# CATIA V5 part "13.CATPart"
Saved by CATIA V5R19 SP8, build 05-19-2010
Part number: 13
Bounding box of the stored display mesh (mm): x -490 to -260.023, y 254.1 to 685.9, z -435.705 to -4.295
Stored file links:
  G:\EU_thinkMotion\CFAO_2010\MMS_groupe3\MMS_groupe3\A reprendre\bblot\BLOT\13.CATPart
  J:\CFAO_IFMA\Amortisseur.CATProduct
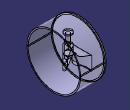
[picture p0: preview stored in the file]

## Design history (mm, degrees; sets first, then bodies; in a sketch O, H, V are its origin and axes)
Set1
  Point1 "F": linked copy from another document
  Line1 "as (BF)": linked copy from another document
  Point2 "D": linked copy from another document
  Line2 "ap": linked copy from another document
Set2
  Plane1: type OffsetPt, RefPlane yz-plane, RefPoint Point1
  Line3: type PtDir, RefPoint Point1, Direction Line2, Start 0, End 20
  Plane2: type OffsetPt, RefPlane Plane3, RefPoint Point2
  Plane3: stored without definition
  Line4 "D\"F\"": stored without definition
  DatumCurve1
  Plane4: stored without definition
  Plane5: type OffsetPt, RefPlane Plane6, RefPoint Point3
  Point3 "D": stored without definition
  Plane6 "Fig.3": stored without definition
Body1 (main body)
  Sketch1 on Plane1, origin (-400, 0, 0), H (0, 1, 0), V (0, 0, 1)
    line L1 (470, -220) -> (500, -220)
    line L2 (500, -220) -> (500, -160)
    line L3 (500, -160) -> (485, -160)
    line L4 (485, -160) -> (485, -80)
    line L5 (485, -80) -> (500, -80)
    point P6 (500, -80)
    line L6 (500, -80) -> (500, -70)
    line L7 (500, -70) -> (470, -70)
    line L8 (470, -70) -> (470, -220)
    reference projected point E1 (470, -220) from Line1
    construction line L9 (470, -249.3526) -> (470, -220)
    point P9 (470, -249.3526)
    axis line L10 (570, -190) -> (500, -190)
    point P10 (570, -190)
    point P11 (500, -190)
    reference projected point E2 (570, -190) from Point2
    distance L8 L4 = 15
    length L2 = 60
    length L6 = 10
    length L1 = 30
    length L4 = 80
    horizontal: L1 H, L3 H, L5 H, L7 H, L10 H
    vertical: L2 V, L4 V, L6 V, L8 V, L9 V
    coincidence: P6 L2, L8 E1, P9 L8, P10 E2, L2 L6
    midpoint: P11 L2
  Shaft1: profile Sketch1, axis Line3, angle 360
  Sketch2 on face of Shaft1 from Sketch1.L3, origin (0, 0, -160), H (1, 0, 0), V (0, 1, 0)
    arc A1 centre (-400, 470) radius 30 from (-415.2552, 495.8317) to (-378.9456, 448.6292) ccw
    line L1 (-415.2552, 495.8317) -> (-275.0851, 578.6106)
    arc A2 centre (-270, 570) radius 10 from (-262.9819, 562.8764) to (-275.0851, 578.6106) ccw
    point P4 (-270, 570)
    reference projected circle E1 centre (-400, 470) radius 30 from edge [face of Shaft1 from Sketch1.L6 | face of Shaft1 from Sketch1.L7]
    reference projected point E2 (-270, 570) from Point2
    reference projected point E3 (-270, 570) from Point2
    line L2 (-262.9819, 562.8764) -> (-378.9456, 448.6292)
    radius A2 = 10
    tangency: L1 A1, A2 L1, L2 A2, L2 A1
    coincidence: A1 E1, P4 E2, P4 E3
  Pad1: profile Sketch2, direction (0, 0, 1), up to face of Shaft1 from Sketch1.L1
  SolidCombine1: FirstComponentProfile Sketch6, FirstComponentDirection Sketch6, SecondComponentProfile Sketch7, SecondComponentDirection Sketch7
  Sketch3 on face of SolidCombine1 from Sketch7.L1, origin (-480, 0, 0), H (0, -1, 0), V (0, 0, 1)
    circle A1 centre (-470, -220) radius 215.9
    point P1 (-470, -220)
    reference projected line E1 through (-470, 0) direction (0, 1) from Line3
    reference projected point E2 (-470, -220) from Line1
    radius A1 = 215.9
    coincidence: P1 E1, P1 E2
  Pad2: profile Sketch3, direction (-1, 0, 0), length 10
  Sketch4 on start face of Pad2, origin (-480, 0, 0), H (0, 1, 0), V (0, 0, 1)
    circle A1 centre (470, -220) radius 215.9
    reference projected circle E1 centre (470, -220) radius 215.9 from edge [start face of Pad2 | face of Pad2 from Sketch3.A1]
    circle A2 centre (470, -220) radius 205.9
    distance A2 A1 = 10
    coincidence: A1 E1
    concentricity: A2 A1
  Pad3: profile Sketch4, direction (1, 0, 0), length 195
  Sketch5 on Plane2, origin (0, 0, -190), H (1, 0, 0), V (0, 1, 0)
    line L1 (-270.8385, 587.4913) -> (-253.309, 564.7029)
    line L2 (-253.309, 564.7029) -> (-288.9771, 537.266)
    line L3 (-288.9771, 537.266) -> (-306.5066, 560.0543)
    line L4 (-306.5066, 560.0543) -> (-270.8385, 587.4913)
    point P3 (-288.9771, 537.266)
    point P4 (-306.5066, 560.0543)
    reference projected line E1 (-400, 470) -> (-270, 570) from Line4
    reference projected arc E2 centre (-270, 570) radius 10 from (-262.9819, 562.8764) to (-275.0851, 578.6106) ccw from edge [face of Pad1 from Sketch2.A2 | start face of Pad1]
    reference projected line E3 (-275.0851, 578.6106) -> (-415.2552, 495.8317) from edge [face of Pad1 from Sketch2.L1 | face of Shaft1]
    reference projected line E4 (-378.9456, 448.6292) -> (-262.9819, 562.8764) from edge [face of Pad1 from Sketch2.L2 | face of Shaft1]
    length L4 = 45
    parallelism: L4 L2, L1 L3, L4 E1
    perpendicularity: L1 L2
    tangency: E2 L1
    coincidence: P4 E3, P3 E4
  Pocket1: profile Sketch5, direction (0, 0, -1), length 20, opposite side length 20
  Sketch6 on Plane4, origin (0, 470, 0), H (-1, 0, 0), V (0, 0, 1)
    arc A1 centre (455, -220) radius 25 from (430, -220) to (480, -220) ccw
    point P1 (455, -220)
    arc A2 centre (370, -250) radius 30 from (400, -250) to (370, -220) ccw
    point P2 (370, -250)
    construction line L1 (370, -250) -> (370, -220)
    point P3 (370, -220)
    reference projected point E1 (370, -220) from vertex [element of Sketch7 | element of Sketch7]
    reference projected line E2 through (0, -220) direction (-1, 0) from Line1
    reference projected line E3 through (400, 0) direction (0, 1) from Line3
    construction line L2 (460, -250) -> (370, -250)
    construction line L3 (460, -250) -> (460, -330)
    axis line L4 (480, -220) -> (480, -330)
    point P7 (480, -220)
    point P8 (480, -330)
    reference projected point E4 (480, -220) from vertex [element of Sketch7 | element of Sketch7]
    arc A3 centre (460, -330) radius 20 from (480, -330) to (460, -310) ccw
    point P9 (460, -310)
    line L5 (480, -330) -> (480, -220)
    line L6 (430, -220) -> (370, -220)
    point P11 (480, -330)
    arc A4 centre (460, -250) radius 60 from (400, -250) to (460, -310) ccw
    point P13 (400, -250)
    point P14 (400, -250)
    reference projected line E5 through (0, -220) direction (-1, 0) from Line1
    distance L3 L5 = 20
    radius A1 = 25
    coincidence: E1 P3, L2 P2, P7 E4, A3 P9, P9 L3, P8 A3, L4 P11, A2 P13, L2 P14, P1 E5, P13 P14, P8 P11
    vertical: L1 V, L3 V, L4 V
    tangency: A2 E2, A2 E3, L4 A3, L5 A3, L6 A2, A1 L5, A3 A4, A4 A2
    horizontal: L2 H
  Sketch7 on face of Shaft1, origin (0, 0, -220), H (1, 0, 0), V (0, -1, 0)
    arc A1 centre (-400, -470) radius 30 from (-370, -470) to (-400, -440) ccw
    reference projected circle E1 centre (-400, -470) radius 30 from edge [face of Shaft1 | face of Pad1]
    arc A2 centre (-400, -360) radius 80 from (-480, -360) to (-400, -440) ccw
    line L1 (-480, -360) -> (-480, -470)
    point P3 (-480, -360)
    point P4 (-480, -470)
    reference projected line E2 through (0, -470) direction (1, 0) from Line1
    construction line L2 (-400, -470) -> (-400, -360)
    reference projected arc E3 centre (-400, -470) radius 40 from (-370, -443.5425) to (-370, -496.4575) ccw from edge of DatumCurve1
    point P5 (-400, -440)
    axis line L3 (-370, -470) -> (-480, -470)
    point P6 (-370, -470)
    reference projected line E4 through (0, -470) direction (1, 0) from edge of Line1
    point P9 (-400, -500)
    point P10 (-370, -470)
    arc A3 centre (-400, -470) radius 30 from (-370, -470) to (-400, -500) cw
    point P12 (-480, -580)
    arc A4 centre (-400, -580) radius 80 from (-480, -580) to (-400, -500) cw
    point P14 (-480, -470)
    line L4 (-480, -580) -> (-480, -470)
    distance E3 L1 = 40
    coincidence: A1 E1, P4 E2, P4 P14, P6 P10
    tangency: A2 A1, L1 A2
    vertical: L1 V, L2 V
    horizontal: L3 H
    symmetry: P5 P9 E4, P6 P10 E4, A1 A3 E4, P3 P12 E4, A2 A4 E4, P4 P14 E4, L1 L4 E4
